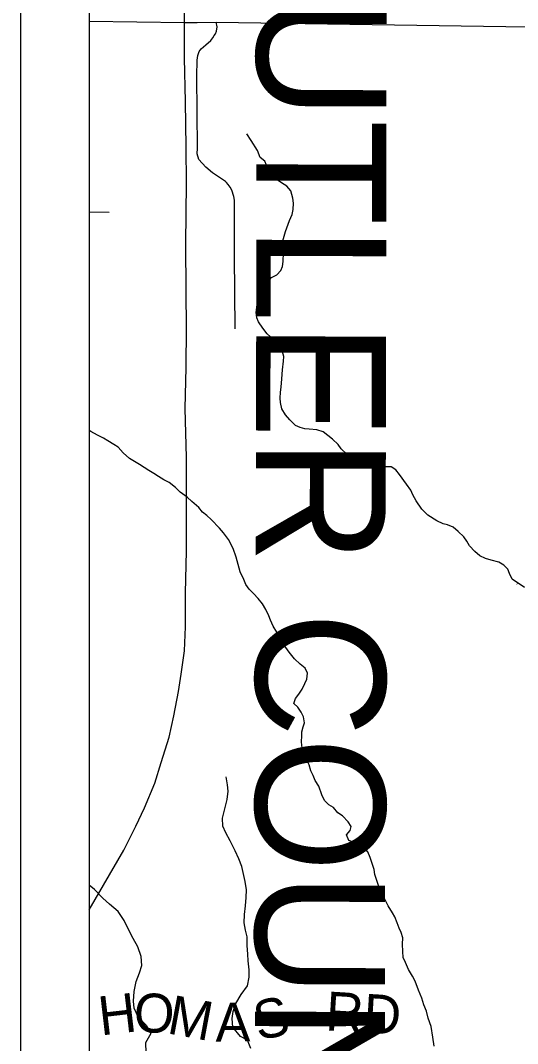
# Model space of a CAD drawing. Extents: x -7.3 to 34, y 0 to 22.
# Drawn here: x 2 to 2.725, y 18.213 to 19.706 of the extents above; entities that cross this region are included whole.
import ezdxf

# ---------------------------------------------------------------- set-up
doc = ezdxf.new("R2010")
doc.units = 0
for name, color, linetype in [('GM_X_Corporation', 7, 'Continuous'), ('GM_X_County_Text', 7, 'Continuous'), ('GM_X_Minor_River', 7, 'Continuous'), ('GM_X_State_Route', 7, 'Continuous'), ('GM_X_Township_Road', 7, 'Continuous'), ('GM_X_Township_Road_Text', 7, 'Continuous'), ('SH_Data', 7, 'Continuous')]:
    doc.layers.add(name, color=color, linetype=linetype)

msp = doc.modelspace()

# ---------------------------------------------------------------- linework, layer by layer
at = {"layer": 'GM_X_Corporation'}
for points in [[(2.1, 20.0921), (2.1, 14.1)], [(2.1, 20.0921), (2.1, 17.0429)]]:
    msp.add_lwpolyline(points, dxfattribs=at)
at = {"layer": 'GM_X_Minor_River'}
for points in [[(2.7353, 18.8784), (2.7173, 18.8907), (2.7132, 18.8988), (2.7106, 18.9052), (2.705, 18.9114), (2.6974, 18.9156), (2.6865, 18.9184), (2.6782, 18.9211), (2.6699, 18.925), (2.6628, 18.9311), (2.6549, 18.9395), (2.6508, 18.9464), (2.6467, 18.9525), (2.6384, 18.9602), (2.6309, 18.9667), (2.623, 18.9702), (2.6165, 18.9714), (2.6071, 18.9756), (2.5939, 18.9841), (2.5853, 18.9929), (2.5771, 19.0051), (2.5722, 19.0139), (2.5692, 19.0204), (2.5629, 19.0295), (2.5528, 19.0433), (2.5472, 19.0502), (2.5404, 19.0544), (2.5283, 19.0545), (2.5181, 19.0565), (2.5094, 19.0593), (2.5022, 19.0612), (2.4932, 19.0636), (2.4822, 19.0667), (2.4758, 19.0729), (2.4676, 19.0809), (2.4635, 19.087), (2.4552, 19.0947), (2.4481, 19.1004), (2.4413, 19.1054), (2.4322, 19.1085), (2.4209, 19.1094), (2.4145, 19.1102), (2.4077, 19.1118), (2.4009, 19.1149), (2.3926, 19.1233), (2.3866, 19.1302), (2.3814, 19.1394), (2.3792, 19.1485), (2.3789, 19.1549), (2.3793, 19.1633), (2.3801, 19.1709), (2.381, 19.183), (2.3822, 19.1959), (2.3838, 19.2088), (2.3842, 19.2156), (2.3816, 19.2236), (2.3764, 19.2335), (2.3697, 19.24), (2.3599, 19.2485), (2.3535, 19.2569), (2.3472, 19.266), (2.3446, 19.2721), (2.3435, 19.2797), (2.3467, 19.3024), (2.3501, 19.31), (2.3604, 19.3239), (2.3662, 19.3307), (2.3737, 19.3348), (2.3798, 19.3408), (2.3822, 19.3469), (2.3833, 19.3541), (2.3838, 19.3666), (2.3827, 19.3768), (2.3824, 19.3841), (2.3847, 19.3912), (2.3863, 19.3977), (2.3925, 19.4139), (2.3963, 19.4226), (2.3975, 19.4298), (2.398, 19.4393), (2.3972, 19.4465), (2.3943, 19.4572), (2.3883, 19.4637), (2.3808, 19.4687), (2.371, 19.4756), (2.3673, 19.4832), (2.3612, 19.4886), (2.3564, 19.5004), (2.3497, 19.5057), (2.3456, 19.516), (2.3366, 19.5305), (2.3302, 19.5404)], [(2.4078, 18.7668), (2.3996, 18.7745), (2.3921, 18.7844), (2.3831, 18.7963), (2.3738, 18.8135), (2.3685, 18.8222), (2.3648, 18.831), (2.3622, 18.8371), (2.3577, 18.8466), (2.3529, 18.8546), (2.3465, 18.8627), (2.3398, 18.8699), (2.3334, 18.8761), (2.3285, 18.883), (2.3259, 18.8902), (2.3203, 18.9012), (2.3174, 18.9123), (2.3144, 18.9229), (2.31, 18.9355), (2.3036, 18.9485), (2.2961, 18.9584), (2.2905, 18.9653), (2.2781, 18.9779), (2.2717, 18.9837), (2.2657, 18.9887), (2.2601, 18.9955), (2.25, 19.004), (2.2432, 19.0101), (2.233, 19.0174), (2.2259, 19.0243), (2.2169, 19.0316), (2.209, 19.0355), (2.2014, 19.0405), (2.1943, 19.0447), (2.1871, 19.049), (2.1736, 19.0578), (2.1664, 19.0624), (2.1589, 19.0667), (2.1499, 19.0751), (2.1424, 19.0835), (2.1364, 19.087), (2.1273, 19.0924), (2.1209, 19.0966), (2.1123, 19.1009), (2.1025, 19.1059), (2.1, 19.1074)], [(2.7241, 18.8839), (2.7246, 18.8836)], [(2.6035, 18.2096), (2.6013, 18.2229), (2.5988, 18.2385), (2.5947, 18.2503), (2.5921, 18.2606), (2.5884, 18.2697), (2.5855, 18.2796), (2.5806, 18.2914), (2.5758, 18.3044), (2.5717, 18.3117), (2.5657, 18.3216), (2.5613, 18.3319), (2.5579, 18.3391), (2.5576, 18.3479), (2.5573, 18.3585), (2.5574, 18.3676), (2.5551, 18.3752), (2.5525, 18.3817), (2.5492, 18.3893), (2.5459, 18.3981), (2.5425, 18.4042), (2.5361, 18.4141), (2.5306, 18.4259), (2.5242, 18.4378), (2.5201, 18.4496), (2.5168, 18.4599), (2.5157, 18.4675), (2.5124, 18.4774), (2.5102, 18.4846), (2.5068, 18.493), (2.4982, 18.5026), (2.4869, 18.5065), (2.479, 18.5096), (2.4756, 18.5179), (2.4806, 18.524), (2.4821, 18.53), (2.478, 18.5369), (2.4694, 18.5457), (2.463, 18.55), (2.4566, 18.5576), (2.4498, 18.5618), (2.4435, 18.568), (2.4394, 18.576), (2.4353, 18.5886), (2.4297, 18.5973), (2.4267, 18.6046), (2.4237, 18.6114), (2.4211, 18.6198), (2.4156, 18.6305), (2.4122, 18.6366), (2.4104, 18.648), (2.41, 18.6541), (2.4101, 18.6617), (2.4105, 18.6681), (2.4125, 18.6753), (2.414, 18.6814), (2.413, 18.6901), (2.4096, 18.6966), (2.4047, 18.7042), (2.3987, 18.7092), (2.401, 18.7168), (2.406, 18.7232), (2.4106, 18.7304), (2.4148, 18.7387), (2.4175, 18.7447), (2.4187, 18.7535), (2.415, 18.7611), (2.4078, 18.7668)], [(2.336, 18.2063), (2.3313, 18.2186), (2.3208, 18.2237), (2.3097, 18.2372), (2.3089, 18.2502), (2.3102, 18.26), (2.3143, 18.2721), (2.3221, 18.2849), (2.3312, 18.2976), (2.3337, 18.3101), (2.3336, 18.3208), (2.3323, 18.3341), (2.3314, 18.3436), (2.3305, 18.3566), (2.3304, 18.3691), (2.3284, 18.3787), (2.3263, 18.3893), (2.3266, 18.4015), (2.328, 18.4144), (2.329, 18.4265), (2.3297, 18.4375), (2.3276, 18.4498), (2.3228, 18.4719), (2.3185, 18.483), (2.3131, 18.4945), (2.3058, 18.5091), (2.2996, 18.5206), (2.2953, 18.5306), (2.2944, 18.542), (2.2981, 18.556), (2.3014, 18.5693), (2.3028, 18.5814), (2.3019, 18.5909), (2.3002, 18.6023)], [(2.1833, 18.2402), (2.1718, 18.2526), (2.166, 18.2653), (2.1647, 18.2752), (2.1657, 18.2893), (2.1687, 18.3041), (2.1735, 18.3166), (2.1771, 18.3275), (2.1762, 18.3405), (2.1712, 18.3543), (2.1646, 18.3666), (2.1577, 18.38), (2.1511, 18.3927), (2.1423, 18.4062), (2.13, 18.4167), (2.1199, 18.4257), (2.108, 18.4381), (2.1, 18.4446)], [(2.1833, 18.2402), (2.19, 18.2279), (2.1825, 18.2144), (2.1829, 18.2003)]]:
    msp.add_lwpolyline(points, dxfattribs=at)
at = {"layer": 'GM_X_State_Route'}
for points in [[(2.2391, 19.7025), (2.2394, 19.7842), (2.2396, 19.8672), (2.24, 19.9473), (2.2404, 20.0258), (2.2402, 20.0886)], [(2.1, 18.4086), (2.1509, 18.4953), (2.1684, 18.5305), (2.1807, 18.5572), (2.1961, 18.593), (2.2054, 18.6234), (2.2171, 18.6605), (2.2238, 18.6915), (2.2307, 18.7268), (2.2344, 18.7521), (2.2391, 18.786), (2.2407, 18.8214), (2.2409, 18.8701), (2.2423, 18.9321), (2.2421, 19.0682), (2.2401, 19.1396), (2.2417, 19.1996), (2.2421, 19.2574), (2.2415, 19.3101), (2.2411, 19.3797), (2.2419, 19.4681), (2.2415, 19.5208), (2.2409, 19.5874), (2.2391, 19.6506), (2.2391, 19.7025)]]:
    msp.add_lwpolyline(points, dxfattribs=at)
at = {"layer": 'GM_X_Township_Road'}
msp.add_line((2.1, 19.4264), (2.1296, 19.4262), dxfattribs=at)
for points in [[(2.1, 19.7045), (2.2391, 19.7025), (2.2576, 19.7027)], [(2.3131, 19.256), (2.3123, 19.3617), (2.3123, 19.4437), (2.3114, 19.4487), (2.3083, 19.4582), (2.3057, 19.4626), (2.3029, 19.4666), (2.3007, 19.4692), (2.299, 19.4709), (2.28, 19.4833), (2.2701, 19.4914), (2.26, 19.503), (2.2579, 19.5111), (2.2584, 19.5195), (2.2572, 19.6244), (2.2577, 19.6479), (2.2587, 19.6545), (2.2606, 19.6602), (2.2634, 19.6643), (2.2702, 19.6702), (2.2775, 19.6765), (2.2804, 19.6801), (2.2827, 19.6836), (2.2843, 19.6863), (2.2859, 19.6902), (2.2868, 19.6962), (2.2853, 19.7031)], [(2.2576, 19.7027), (2.2853, 19.7031), (2.7404, 19.6961)]]:
    msp.add_lwpolyline(points, dxfattribs=at)
at = {"layer": 'SH_Data'}
for p, q in [((2, 21), (2, 14)), ((2.1, 20.9), (2.1, 14.1))]:
    msp.add_line(p, q, dxfattribs=at)

# ---------------------------------------------------------------- texts
at = {"layer": 'GM_X_County_Text'}
msp.add_text('BUTLER COUNTY', height=0.189394, rotation=269.9014, dxfattribs=at).set_placement((2.3449, 19.913))
at = {"layer": 'GM_X_Township_Road_Text'}
for s, height, rotation, p in [('H', 0.0568, 6.6447, (2.1171, 18.2251)), ('O', 0.0568, 357.3617, (2.1643, 18.2308)), ('M', 0.0568, 349.4191, (2.2122, 18.2287)), ('S', 0.0568, 11.4433, (2.3465, 18.2179)), ('RD', 0.05682, 356.5467, (2.4439, 18.2328)), ('A', 0.0568, 0.3576, (2.2846, 18.2163))]:
    msp.add_text(s, height=height, rotation=rotation, dxfattribs=at).set_placement(p)

doc.saveas('drawing.dxf')
